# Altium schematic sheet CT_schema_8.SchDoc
size 371 x 245 mm
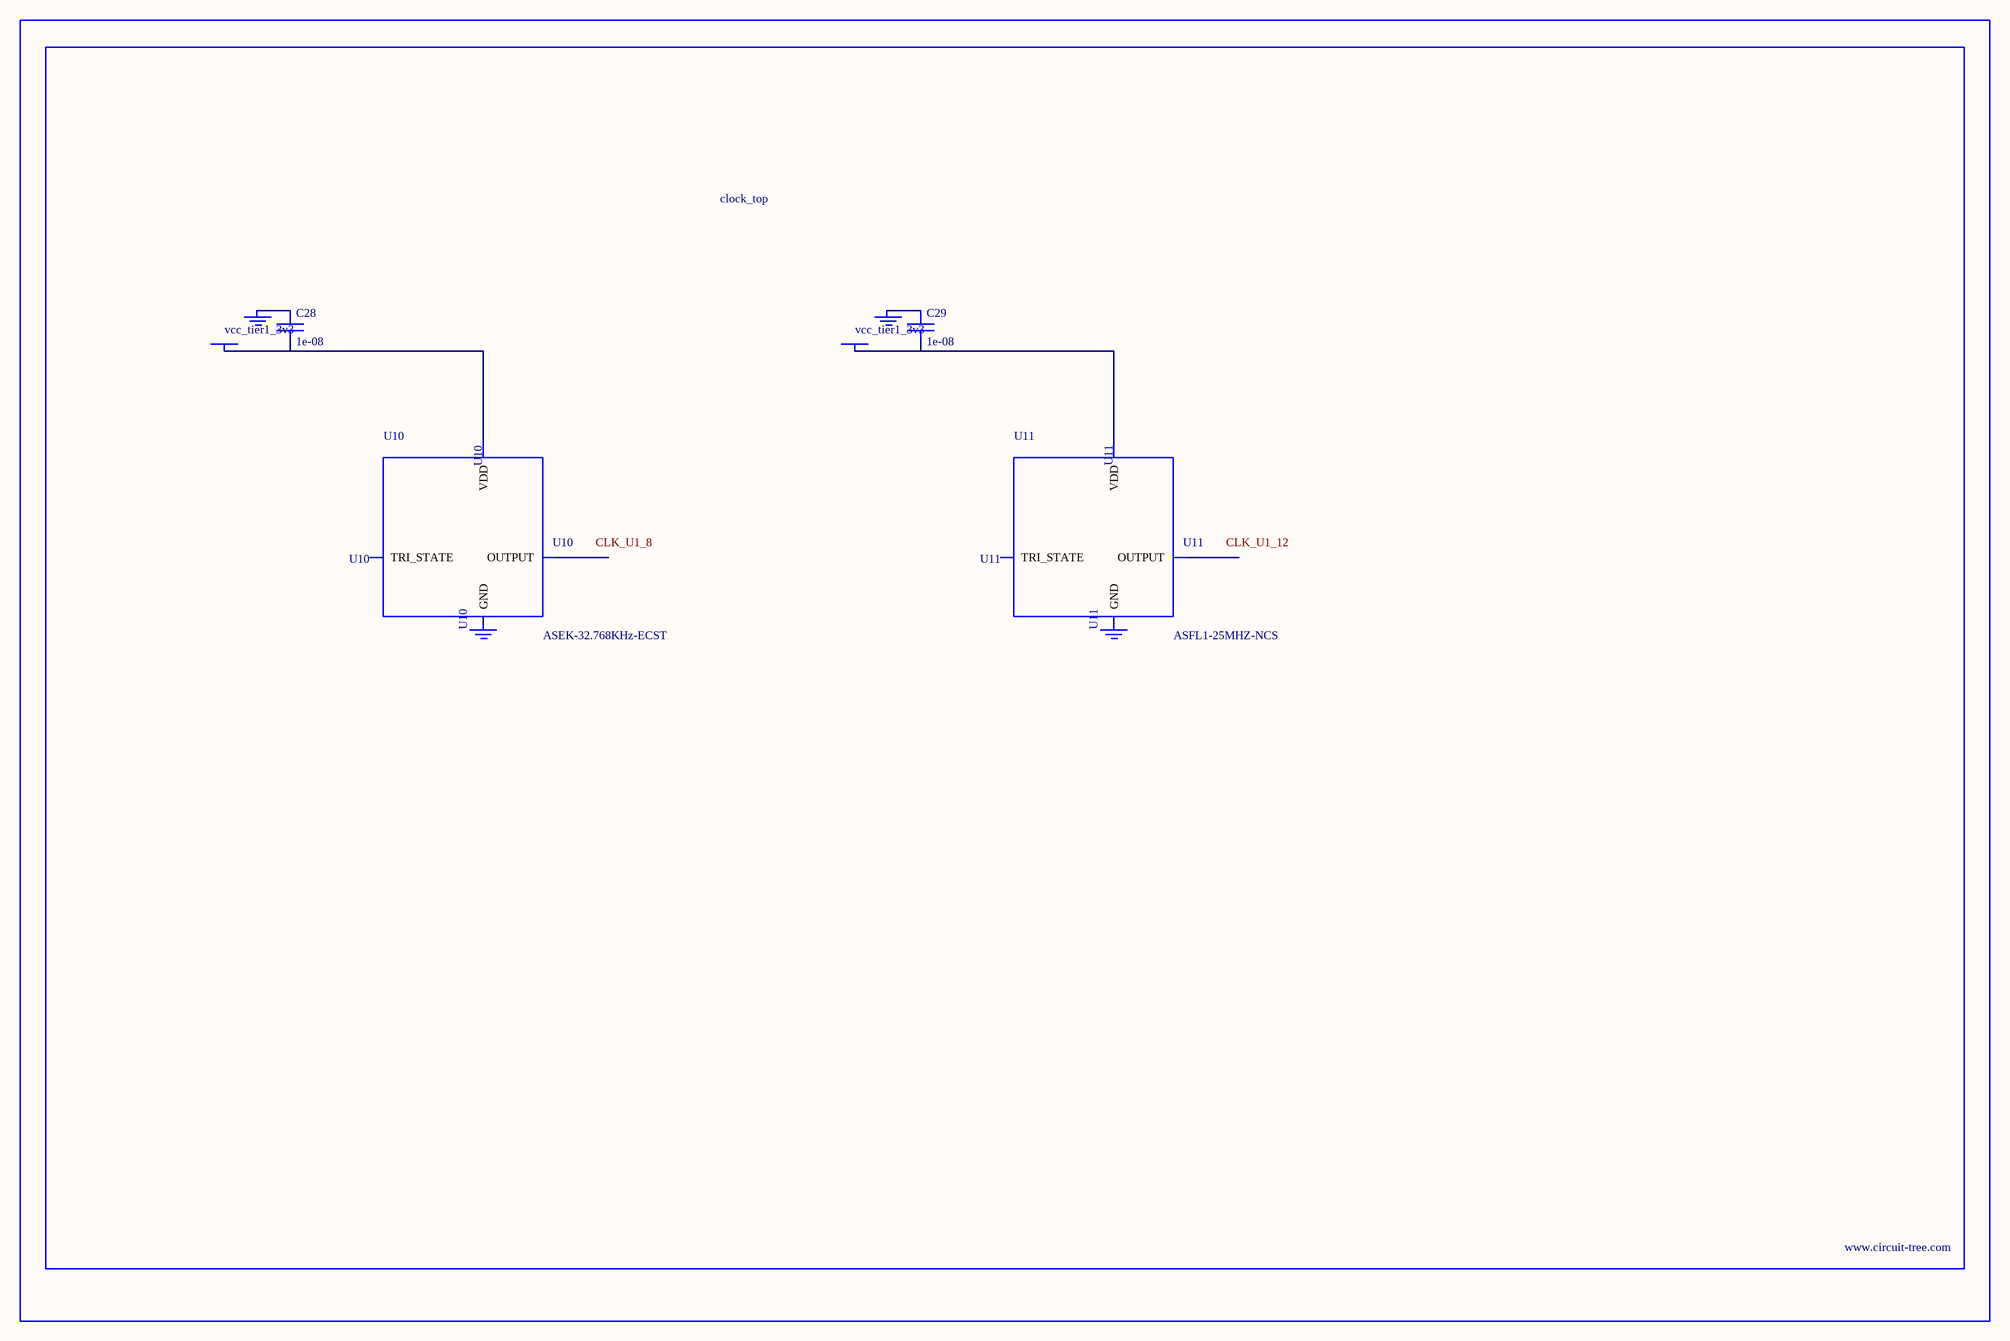
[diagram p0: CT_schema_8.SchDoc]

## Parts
BORDER7  (no value)
C28  1e-08  [C0402]
C29  1e-08  [C0402]
GND_INSTANCE_7_0  (no value)
GND_INSTANCE_7_1  (no value)
GND_INSTANCE_7_2  (no value)
GND_INSTANCE_7_3  (no value)
POWER_INSTANCE_7_0  vcc_tier1_3v3
POWER_INSTANCE_7_1  vcc_tier1_3v3
U10  ASEK-32.768KHz-ECST  [ASEK]
U11  ASFL1-25MHZ-NCS  [ASFL1]

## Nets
NetC28_1: C28.1 GND_INSTANCE_7_0.0(GND)
NetC28_2: C28.2 POWER_INSTANCE_7_0.0(PWR) U10.4(VDD)
NetC29_1: C29.1 GND_INSTANCE_7_2.0(GND)
NetC29_2: C29.2 POWER_INSTANCE_7_1.0(PWR) U11.4(VDD)

Not connected (* = marked no-connect by the designer): GND_INSTANCE_7_1 0(GND); GND_INSTANCE_7_3 0(GND); U10 1(TRI_STATE) 2(GND) 3(OUTPUT); U11 1(TRI_STATE) 2(GND) 3(OUTPUT)

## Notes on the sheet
- Labels drawn without touching a wire or pin: CLK_U1_8, CLK_U1_12

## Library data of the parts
BORDER7 = BORDER_PAGE7
C28 C29 = C0402C103K3RAC
GND_INSTANCE_7_0-GND_INSTANCE_7_3 = GND
POWER_INSTANCE_7_0 POWER_INSTANCE_7_1 = PWR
